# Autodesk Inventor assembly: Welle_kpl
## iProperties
Shininess: 64.0
Length Units: 11269
Angle Units: 11279
Time Units: 11290
Mass Units: 11283
Length Display Precision: 3
Angle Display Precision: 2
Compacted: True
Created: 2004-05
Part Number: Welle_kpl
Document SubType Name: Assembly
Designer: KWU_CAD
Manufacturer: Standard
Standards Organization: Custom
Density: 0.0
Volumn: 0.0
Area: 0.0
PropertySet Name: Model Information
Control State: 0
Master: False
Checked Out: False
Author: KWU_CAD
